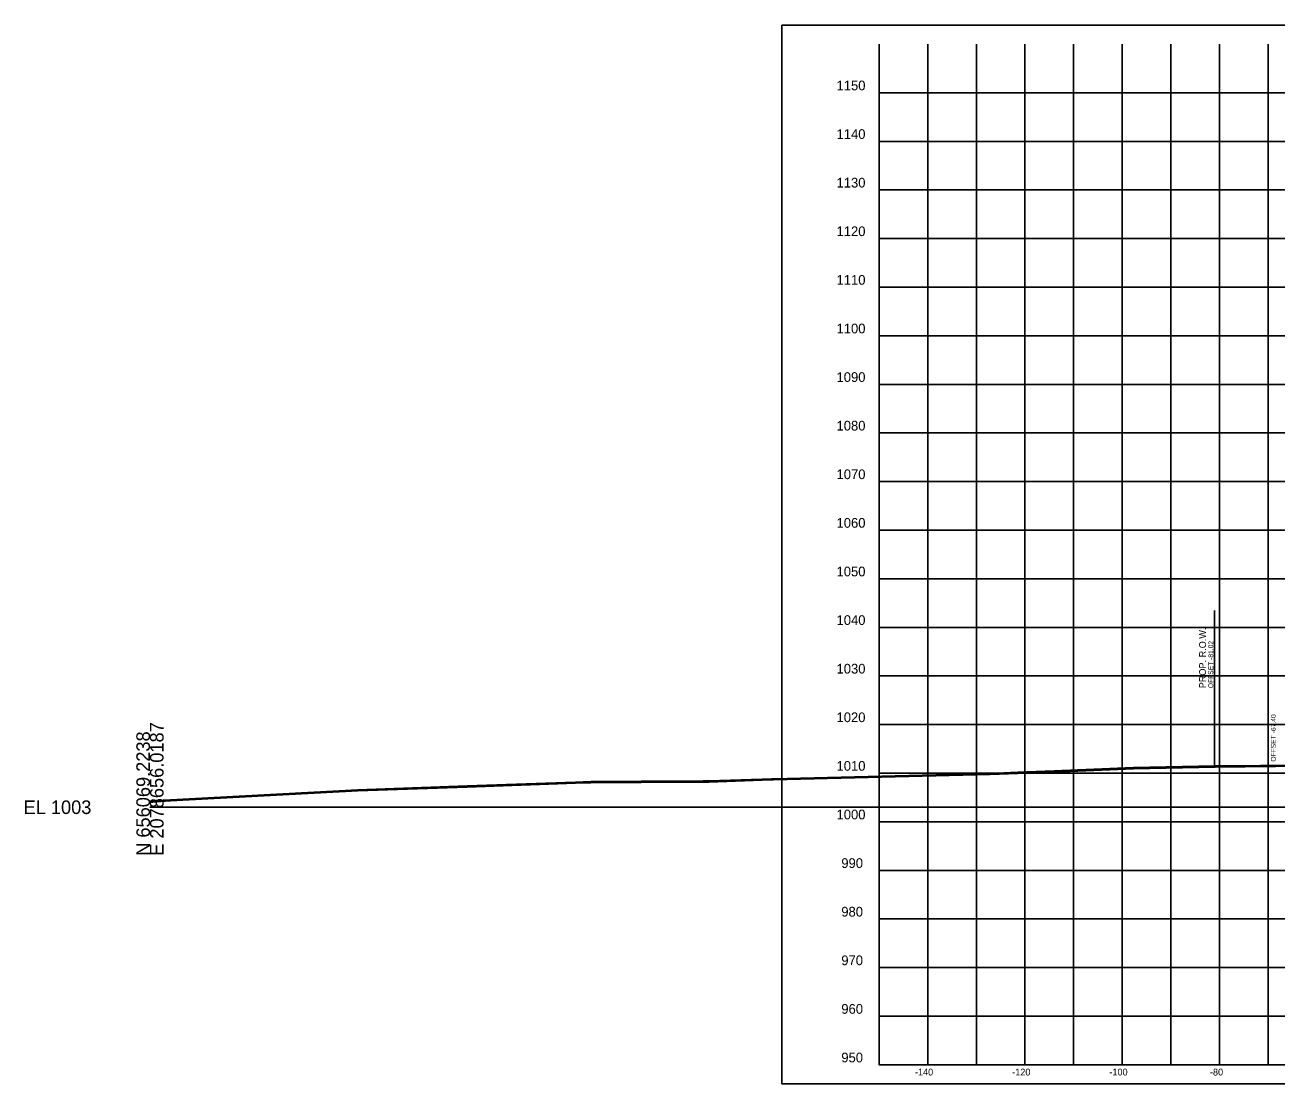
# Model space of a CAD drawing. Extents: x 1131015 to 1136271, y 133453 to 174329.
# Drawn here: x 1131014.8 to 1131272.3, y 157610.7 to 157828.6 of the extents above; entities that cross this region are included whole.
import ezdxf

# ---------------------------------------------------------------- set-up
doc = ezdxf.new("R2010")
doc.units = 0
for name, color, linetype in [('DESIGN - ROW - Right-of-Way and Easement Labels', 7, 'Continuous'), ('DESIGN - ROW - Right-of-Way Linework', 7, 'Continuous'), ('DESIGN - SHEET - Corner Text', 7, 'Continuous'), ('DESIGN - SHEET - Light Grid', 7, 'Continuous'), ('DESIGN - SHEET - Linework', 7, 'Continuous'), ('DESIGN - SHEET - Plot Shape', 7, 'Continuous'), ('DESIGN - TYPICAL - Slope Tie Text', 7, 'Continuous'), ('SURVEY - GROUND - Bottom of Topsoil Layer', 7, 'Continuous'), ('SURVEY - GROUND - Top of Ground', 7, 'Continuous')]:
    doc.layers.add(name, color=color, linetype=linetype)

msp = doc.modelspace()

# ---------------------------------------------------------------- linework, layer by layer
at = {"layer": 'DESIGN - ROW - Right-of-Way Linework'}
msp.add_line((1131259.44, 157676.14), (1131259.44, 157708.14), dxfattribs=at)
at = {"layer": 'DESIGN - SHEET - Light Grid'}
msp.add_line((1131040.46, 157667.66), (1131340.46, 157667.66), dxfattribs=at)
at = {"layer": 'DESIGN - SHEET - Linework'}
for p, q in [((1131200.46, 157614.66), (1131200.46, 157824.66)), ((1131210.46, 157614.66), (1131210.46, 157824.66)), ((1131220.46, 157614.66), (1131220.46, 157824.66)), ((1131230.46, 157614.66), (1131230.46, 157824.66)), ((1131240.46, 157614.66), (1131240.46, 157824.66)), ((1131250.46, 157614.66), (1131250.46, 157824.66)), ((1131260.46, 157614.66), (1131260.46, 157824.66)), ((1131270.46, 157614.66), (1131270.46, 157824.66)), ((1131190.46, 157814.66), (1131490.46, 157814.66)), ((1131190.46, 157804.66), (1131490.46, 157804.66)), ((1131190.46, 157794.66), (1131490.46, 157794.66)), ((1131190.46, 157784.66), (1131490.46, 157784.66)), ((1131190.46, 157774.66), (1131490.46, 157774.66)), ((1131190.46, 157764.66), (1131490.46, 157764.66)), ((1131190.46, 157754.66), (1131490.46, 157754.66)), ((1131190.46, 157744.66), (1131490.46, 157744.66)), ((1131190.46, 157734.66), (1131490.46, 157734.66)), ((1131190.46, 157724.66), (1131490.46, 157724.66)), ((1131190.46, 157714.66), (1131490.46, 157714.66)), ((1131190.46, 157704.66), (1131490.46, 157704.66)), ((1131190.46, 157694.66), (1131490.46, 157694.66)), ((1131190.46, 157684.66), (1131490.46, 157684.66)), ((1131190.46, 157674.66), (1131490.46, 157674.66)), ((1131190.46, 157664.66), (1131490.46, 157664.66)), ((1131190.46, 157654.66), (1131490.46, 157654.66)), ((1131190.46, 157644.66), (1131490.46, 157644.66)), ((1131190.46, 157634.66), (1131490.46, 157634.66)), ((1131190.46, 157624.66), (1131490.46, 157624.66))]:
    msp.add_line(p, q, dxfattribs=at)
msp.add_lwpolyline([(1131190.46, 157824.66), (1131190.46, 157614.66), (1131490.46, 157614.66), (1131490.46, 157824.66)], dxfattribs=at)
at = {"layer": 'DESIGN - SHEET - Plot Shape'}
msp.add_lwpolyline([(1131170.46, 157828.6), (1131510.46, 157828.6), (1131510.46, 157610.72), (1131170.46, 157610.72)], close=True, dxfattribs=at)
at = {"layer": 'SURVEY - GROUND - Bottom of Topsoil Layer'}
for p, q in [((1131168.71, 157673.28), (1131213.22, 157674.37)), ((1131213.22, 157674.37), (1131218.98, 157674.59)), ((1131218.98, 157674.59), (1131226.48, 157674.86)), ((1131226.48, 157674.86), (1131242.82, 157675.58)), ((1131242.82, 157675.58), (1131259.59, 157675.89)), ((1131259.59, 157675.89), (1131278.56, 157676.09)), ((1131083.2, 157671), (1131105.74, 157671.81)), ((1131105.74, 157671.81), (1131128.03, 157672.58)), ((1131128.03, 157672.58), (1131131.15, 157672.7)), ((1131131.15, 157672.7), (1131141.51, 157672.76)), ((1131141.51, 157672.76), (1131154.27, 157672.81)), ((1131154.27, 157672.81), (1131155.47, 157672.83)), ((1131155.47, 157672.83), (1131166.41, 157673.19)), ((1131166.41, 157673.19), (1131168.34, 157673.27)), ((1131168.34, 157673.27), (1131168.71, 157673.28)), ((1131040.46, 157668.63), (1131041.68, 157668.77)), ((1131041.68, 157668.77), (1131044.7, 157668.94)), ((1131044.7, 157668.94), (1131083.2, 157671))]:
    msp.add_line(p, q, dxfattribs=at)
at = {"layer": 'SURVEY - GROUND - Top of Ground'}
for p, q in [((1131259.59, 157676.14), (1131278.56, 157676.34)), ((1131168.71, 157673.53), (1131213.22, 157674.62)), ((1131213.22, 157674.62), (1131218.98, 157674.84)), ((1131218.98, 157674.84), (1131226.48, 157675.11)), ((1131226.48, 157675.11), (1131242.82, 157675.83)), ((1131242.82, 157675.83), (1131259.59, 157676.14)), ((1131044.7, 157669.19), (1131083.2, 157671.25)), ((1131083.2, 157671.25), (1131105.74, 157672.06)), ((1131105.74, 157672.06), (1131128.03, 157672.83)), ((1131128.03, 157672.83), (1131131.15, 157672.95)), ((1131131.15, 157672.95), (1131141.51, 157673.01)), ((1131141.51, 157673.01), (1131154.27, 157673.06)), ((1131154.27, 157673.06), (1131155.47, 157673.08)), ((1131155.47, 157673.08), (1131166.41, 157673.44)), ((1131166.41, 157673.44), (1131168.34, 157673.52)), ((1131168.34, 157673.52), (1131168.71, 157673.53)), ((1131040.46, 157668.88), (1131041.68, 157669.02)), ((1131041.68, 157669.02), (1131044.7, 157669.19))]:
    msp.add_line(p, q, dxfattribs=at)

# ---------------------------------------------------------------- texts
at = {"layer": 'DESIGN - ROW - Right-of-Way and Easement Labels'}
for s, height, p in [('PROP. R.O.W.', 1.4, (1131257.69, 157692.14)), ('OFFSET -81.02', 1, (1131259.19, 157692.14))]:
    msp.add_text(s, height=height, rotation=90, dxfattribs=at).set_placement(p)
at = {"layer": 'DESIGN - SHEET - Corner Text'}
for s, height, p in [('1150', 2, (1131181.7, 157815.16)), ('1140', 2, (1131181.7, 157805.16)), ('1130', 2, (1131181.7, 157795.16)), ('1120', 2, (1131181.7, 157785.16)), ('1110', 2, (1131181.7, 157775.16)), ('1100', 2, (1131181.7, 157765.16)), ('1090', 2, (1131181.7, 157755.16)), ('1080', 2, (1131181.7, 157745.16)), ('1070', 2, (1131181.7, 157735.16)), ('1060', 2, (1131181.7, 157725.16)), ('1050', 2, (1131181.7, 157715.16)), ('1040', 2, (1131181.7, 157705.16)), ('1030', 2, (1131181.7, 157695.16)), ('1020', 2, (1131181.7, 157685.16)), ('1010', 2, (1131181.7, 157675.16)), ('1000', 2, (1131181.7, 157665.16)), ('990', 2, (1131182.68, 157655.16)), ('980', 2, (1131182.68, 157645.16)), ('970', 2, (1131182.68, 157635.16)), ('960', 2, (1131182.68, 157625.16)), ('950', 2, (1131182.68, 157615.16)), ('-140', 1.4, (1131197.83, 157612.46)), ('-120', 1.4, (1131217.83, 157612.46)), ('-100', 1.4, (1131237.83, 157612.46)), ('-80', 1.4, (1131258.51, 157612.46))]:
    msp.add_text(s, height=height, dxfattribs=at).set_placement(p)
at = {"layer": 'DESIGN - SHEET - Light Grid'}
for s, p in [('E 2078656.0187', (1131043.26, 157657.66)), ('N 656069.2238', (1131040.46, 157657.66))]:
    msp.add_text(s, height=2.8, rotation=90, dxfattribs=at).set_placement(p)
msp.add_text('EL 1003', height=2.8, dxfattribs=at).set_placement((1131014.46, 157666.26))
at = {"layer": 'DESIGN - TYPICAL - Slope Tie Text'}
msp.add_text('OFFSET -67.40', height=1, rotation=90, dxfattribs=at).set_placement((1131272.06, 157677.03))

doc.saveas('drawing.dxf')
